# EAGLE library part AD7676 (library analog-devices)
16-Bit, +-1 LSB INL, 500 kSPS, Differential ADC Source: http://www.analog.com/static/imported-files/data_sheets/AD7676.pdf
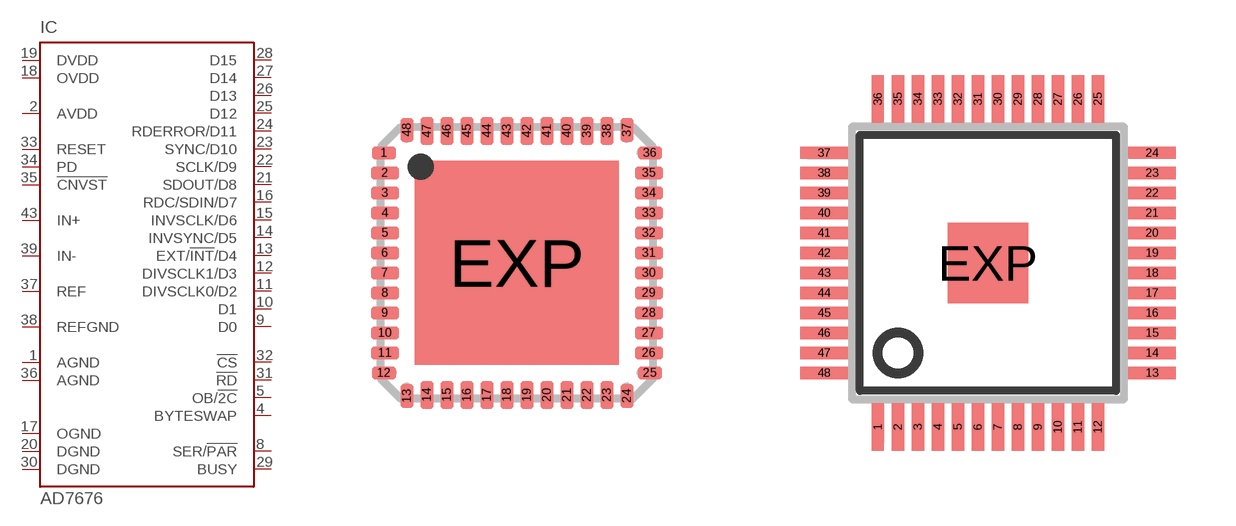
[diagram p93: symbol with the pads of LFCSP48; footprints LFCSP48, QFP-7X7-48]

Designator prefix IC

## AD7676CP (MF: ALTERA CORPORATION; MPN: AD7676ASTZ; OC_FARNELL: 1464604; OC_NEWARK: 59K5190)  [LFCSP48]
1  AGND  in
2  AVDD  in
4  BYTESWAP  in
5  OB/!2C  in
8  SER/!PAR  in
9  D0  out
10  D1  out
11  DIVSCLK0/D2
12  DIVSCLK1/D3
13  EXT/!INT!/D4
14  INVSYNC/D5
15  INVSCLK/D6
16  RDC/SDIN/D7
17  OGND  in
18  OVDD  in
19  DVDD  in
20  DGND  in
21  SDOUT/D8  out
22  SCLK/D9
23  SYNC/D10  out
24  RDERROR/D11  out
25  D12  out
26  D13  out
27  D14  out
28  D15  out
29  BUSY  in
30  DGND  in
31  !RD  in
32  !CS  in
33  RESET  in
34  PD  in
35  !CNVST  in
36  AGND  in
37  REF  in
38  REFGND  in
39  IN-  in
43  IN+  in

## AD7676ST (MF: ALTERA CORPORATION; MPN: AD7676ASTZRL; OC_FARNELL: unknown; OC_NEWARK: 59K5191)  [QFP-7X7-48]
Pads as for LFCSP48

## Footprint LFCSP48 (pad centres in mm)
Lead Frame Chip Scale Package LFCSP CP-48 COMPLIANT TO JEDEC STANDARDS MO-220-VKKD-2 Source: http://www.analog.com/UploadedFiles/Data_Sheets/39780344872292AD7651_0.pdf
smd 0.6 x 0.32: 1 -3.325,2.75; 12 -3.325,-2.75; 25 3.325,-2.75; 36 3.325,2.75
smd 0.7 x 0.32: 2 -3.3,2.25; 3 -3.3,1.75; 4 -3.3,1.25; 5 -3.3,0.75; 6 -3.3,0.25; 7 -3.3,-0.25; 8 -3.3,-0.75; 9 -3.3,-1.25; 10 -3.3,-1.75; 11 -3.3,-2.25; 26 3.3,-2.25; 27 3.3,-1.75; 28 3.3,-1.25; 29 3.3,-0.75; 30 3.3,-0.25; 31 3.3,0.25; 32 3.3,0.75; 33 3.3,1.25; 34 3.3,1.75; 35 3.3,2.25
smd 0.32 x 0.6: 13 -2.75,-3.325; 24 2.75,-3.325; 37 2.75,3.325; 48 -2.75,3.325
smd 0.32 x 0.7: 14 -2.25,-3.3; 15 -1.75,-3.3; 16 -1.25,-3.3; 17 -0.75,-3.3; 18 -0.25,-3.3; 19 0.25,-3.3; 20 0.75,-3.3; 21 1.25,-3.3; 22 1.75,-3.3; 23 2.25,-3.3; 38 2.25,3.3; 39 1.75,3.3; 40 1.25,3.3; 41 0.75,3.3; 42 0.25,3.3; 43 -0.25,3.3; 44 -0.75,3.3; 45 -1.25,3.3; 46 -1.75,3.3; 47 -2.25,3.3
smd 5.1 x 5.1: EXP 0,0

## Footprint QFP-7X7-48 (pad centres in mm)
TQFP48 7x7 Thin Plastic Quad Flat Package, Exposed Pad, TQFP/EP Source: www.analog.com/UploadedFiles/Data_Sheets/33830397585263AD9859_0.pdf
smd 0.3 x 1.2: 1 -2.75,-4.1; 2 -2.25,-4.1; 3 -1.75,-4.1; 4 -1.25,-4.1; 5 -0.75,-4.1; 6 -0.25,-4.1; 7 0.25,-4.1; 8 0.75,-4.1; 9 1.25,-4.1; 10 1.75,-4.1; 11 2.25,-4.1; 12 2.75,-4.1; 25 2.75,4.1; 26 2.25,4.1; 27 1.75,4.1; 28 1.25,4.1; 29 0.75,4.1; 30 0.25,4.1; 31 -0.25,4.1; 32 -0.75,4.1; 33 -1.25,4.1; 34 -1.75,4.1; 35 -2.25,4.1; 36 -2.75,4.1
smd 1.2 x 0.3: 13 4.1,-2.75; 14 4.1,-2.25; 15 4.1,-1.75; 16 4.1,-1.25; 17 4.1,-0.75; 18 4.1,-0.25; 19 4.1,0.25; 20 4.1,0.75; 21 4.1,1.25; 22 4.1,1.75; 23 4.1,2.25; 24 4.1,2.75; 37 -4.1,2.75; 38 -4.1,2.25; 39 -4.1,1.75; 40 -4.1,1.25; 41 -4.1,0.75; 42 -4.1,0.25; 43 -4.1,-0.25; 44 -4.1,-0.75; 45 -4.1,-1.25; 46 -4.1,-1.75; 47 -4.1,-2.25; 48 -4.1,-2.75
smd 2 x 2: EXP 0,0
